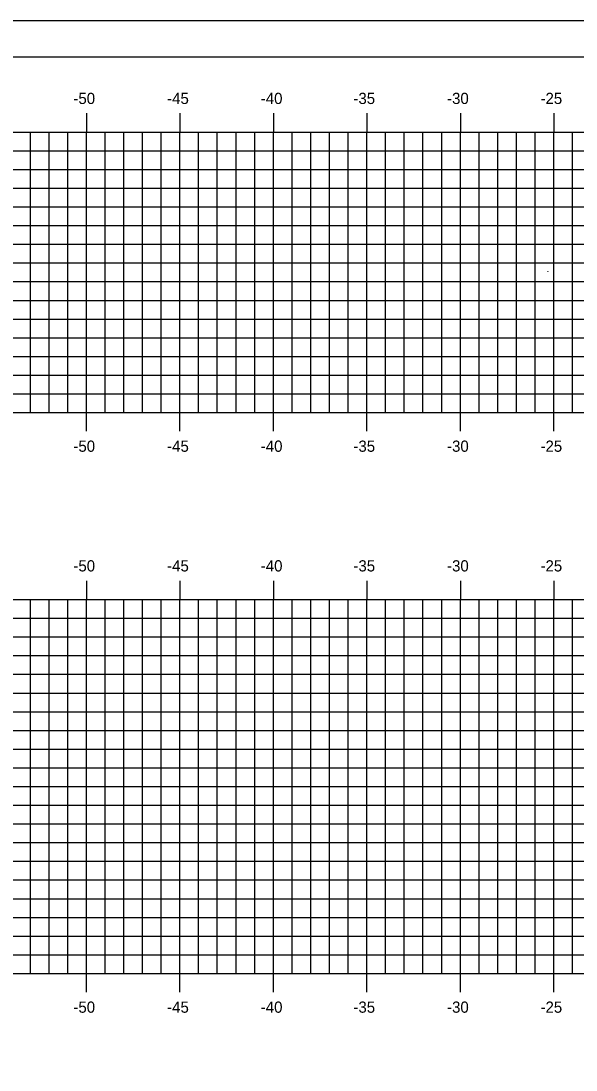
# Model space of a CAD drawing. Extents: x 1026799 to 1026969, y 394697 to 394807.
# Drawn here: x 1026828.8 to 1026858.5, y 394750.4 to 394806.5 of the extents above; entities that cross this region are included whole.
import ezdxf

# ---------------------------------------------------------------- set-up
doc = ezdxf.new("R2010")
doc.units = 0
for name, color, linetype in [('BORDER', 7, 'Continuous'), ('H_V ANNOTATION', 7, 'Continuous'), ('MAJOR', 7, 'Continuous'), ('MINOR', 7, 'Continuous'), ('PLOT BOUNDARY', 7, 'Continuous'), ('S_Utilities_Hydrant', 7, 'Continuous')]:
    doc.layers.add(name, color=color, linetype=linetype)

msp = doc.modelspace()

# ---------------------------------------------------------------- linework, layer by layer
at = {"layer": 'BORDER'}
msp.add_line((1026967.348, 394804.607), (1026807.348, 394804.607), dxfattribs=at)
at = {"layer": 'MAJOR'}
for p, q in [((1026832.348, 394801.609), (1026832.348, 394800.607)), ((1026837.348, 394801.609), (1026837.348, 394800.607)), ((1026842.348, 394801.609), (1026842.348, 394800.607)), ((1026847.348, 394801.609), (1026847.348, 394800.607)), ((1026852.348, 394801.609), (1026852.348, 394800.607)), ((1026857.348, 394801.609), (1026857.348, 394800.607)), ((1026812.348, 394800.607), (1026952.348, 394800.607)), ((1026832.348, 394785.607), (1026832.348, 394800.607)), ((1026837.348, 394785.607), (1026837.348, 394800.607)), ((1026842.348, 394785.607), (1026842.348, 394800.607)), ((1026847.348, 394785.607), (1026847.348, 394800.607)), ((1026852.348, 394785.607), (1026852.348, 394800.607)), ((1026857.348, 394785.607), (1026857.348, 394800.607)), ((1026812.348, 394795.607), (1026952.348, 394795.607)), ((1026812.348, 394790.607), (1026952.348, 394790.607)), ((1026812.348, 394785.607), (1026952.348, 394785.607)), ((1026832.348, 394784.605), (1026832.348, 394785.607)), ((1026837.348, 394784.605), (1026837.348, 394785.607)), ((1026842.348, 394784.605), (1026842.348, 394785.607)), ((1026847.348, 394784.605), (1026847.348, 394785.607)), ((1026852.348, 394784.605), (1026852.348, 394785.607)), ((1026857.348, 394784.605), (1026857.348, 394785.607)), ((1026832.348, 394776.609), (1026832.348, 394775.607)), ((1026837.348, 394776.609), (1026837.348, 394775.607)), ((1026842.348, 394776.609), (1026842.348, 394775.607)), ((1026847.348, 394776.609), (1026847.348, 394775.607)), ((1026852.348, 394776.609), (1026852.348, 394775.607)), ((1026857.348, 394776.609), (1026857.348, 394775.607)), ((1026812.348, 394775.607), (1026952.348, 394775.607)), ((1026832.348, 394755.607), (1026832.348, 394775.607)), ((1026837.348, 394755.607), (1026837.348, 394775.607)), ((1026842.348, 394755.607), (1026842.348, 394775.607)), ((1026847.348, 394755.607), (1026847.348, 394775.607)), ((1026852.348, 394755.607), (1026852.348, 394775.607)), ((1026857.348, 394755.607), (1026857.348, 394775.607)), ((1026812.348, 394770.607), (1026952.348, 394770.607)), ((1026812.348, 394765.607), (1026952.348, 394765.607)), ((1026812.348, 394760.607), (1026952.348, 394760.607)), ((1026812.348, 394755.607), (1026952.348, 394755.607)), ((1026832.348, 394754.605), (1026832.348, 394755.607)), ((1026837.348, 394754.605), (1026837.348, 394755.607)), ((1026842.348, 394754.605), (1026842.348, 394755.607)), ((1026847.348, 394754.605), (1026847.348, 394755.607)), ((1026852.348, 394754.605), (1026852.348, 394755.607)), ((1026857.348, 394754.605), (1026857.348, 394755.607))]:
    msp.add_line(p, q, dxfattribs=at)
at = {"layer": 'MINOR'}
for p, q in [((1026829.348, 394785.607), (1026829.348, 394800.607)), ((1026830.348, 394785.607), (1026830.348, 394800.607)), ((1026831.348, 394785.607), (1026831.348, 394800.607)), ((1026833.348, 394785.607), (1026833.348, 394800.607)), ((1026834.348, 394785.607), (1026834.348, 394800.607)), ((1026835.348, 394785.607), (1026835.348, 394800.607)), ((1026836.348, 394785.607), (1026836.348, 394800.607)), ((1026838.348, 394785.607), (1026838.348, 394800.607)), ((1026839.348, 394785.607), (1026839.348, 394800.607)), ((1026840.348, 394785.607), (1026840.348, 394800.607)), ((1026841.348, 394785.607), (1026841.348, 394800.607)), ((1026843.348, 394785.607), (1026843.348, 394800.607)), ((1026844.348, 394785.607), (1026844.348, 394800.607)), ((1026845.348, 394785.607), (1026845.348, 394800.607)), ((1026846.348, 394785.607), (1026846.348, 394800.607)), ((1026848.348, 394785.607), (1026848.348, 394800.607)), ((1026849.348, 394785.607), (1026849.348, 394800.607)), ((1026850.348, 394785.607), (1026850.348, 394800.607)), ((1026851.348, 394785.607), (1026851.348, 394800.607)), ((1026853.348, 394785.607), (1026853.348, 394800.607)), ((1026854.348, 394785.607), (1026854.348, 394800.607)), ((1026855.348, 394785.607), (1026855.348, 394800.607)), ((1026856.348, 394785.607), (1026856.348, 394800.607)), ((1026858.348, 394785.607), (1026858.348, 394800.607)), ((1026812.348, 394799.607), (1026952.348, 394799.607)), ((1026812.348, 394798.607), (1026952.348, 394798.607)), ((1026812.348, 394797.607), (1026952.348, 394797.607)), ((1026812.348, 394796.607), (1026952.348, 394796.607)), ((1026812.348, 394794.607), (1026952.348, 394794.607)), ((1026812.348, 394793.607), (1026952.348, 394793.607)), ((1026812.348, 394792.607), (1026952.348, 394792.607)), ((1026812.348, 394791.607), (1026952.348, 394791.607)), ((1026812.348, 394789.607), (1026952.348, 394789.607)), ((1026812.348, 394788.607), (1026952.348, 394788.607)), ((1026812.348, 394787.607), (1026952.348, 394787.607)), ((1026812.348, 394786.607), (1026952.348, 394786.607)), ((1026829.348, 394755.607), (1026829.348, 394775.607)), ((1026830.348, 394755.607), (1026830.348, 394775.607)), ((1026831.348, 394755.607), (1026831.348, 394775.607)), ((1026833.348, 394755.607), (1026833.348, 394775.607)), ((1026834.348, 394755.607), (1026834.348, 394775.607)), ((1026835.348, 394755.607), (1026835.348, 394775.607)), ((1026836.348, 394755.607), (1026836.348, 394775.607)), ((1026838.348, 394755.607), (1026838.348, 394775.607)), ((1026839.348, 394755.607), (1026839.348, 394775.607)), ((1026840.348, 394755.607), (1026840.348, 394775.607)), ((1026841.348, 394755.607), (1026841.348, 394775.607)), ((1026843.348, 394755.607), (1026843.348, 394775.607)), ((1026844.348, 394755.607), (1026844.348, 394775.607)), ((1026845.348, 394755.607), (1026845.348, 394775.607)), ((1026846.348, 394755.607), (1026846.348, 394775.607)), ((1026848.348, 394755.607), (1026848.348, 394775.607)), ((1026849.348, 394755.607), (1026849.348, 394775.607)), ((1026850.348, 394755.607), (1026850.348, 394775.607)), ((1026851.348, 394755.607), (1026851.348, 394775.607)), ((1026853.348, 394755.607), (1026853.348, 394775.607)), ((1026854.348, 394755.607), (1026854.348, 394775.607)), ((1026855.348, 394755.607), (1026855.348, 394775.607)), ((1026856.348, 394755.607), (1026856.348, 394775.607)), ((1026858.348, 394755.607), (1026858.348, 394775.607)), ((1026812.348, 394774.607), (1026952.348, 394774.607)), ((1026812.348, 394773.607), (1026952.348, 394773.607)), ((1026812.348, 394772.607), (1026952.348, 394772.607)), ((1026812.348, 394771.607), (1026952.348, 394771.607)), ((1026812.348, 394769.607), (1026952.348, 394769.607)), ((1026812.348, 394768.607), (1026952.348, 394768.607)), ((1026812.348, 394767.607), (1026952.348, 394767.607)), ((1026812.348, 394766.607), (1026952.348, 394766.607)), ((1026812.348, 394764.607), (1026952.348, 394764.607)), ((1026812.348, 394763.607), (1026952.348, 394763.607)), ((1026812.348, 394762.607), (1026952.348, 394762.607)), ((1026812.348, 394761.607), (1026952.348, 394761.607)), ((1026812.348, 394759.607), (1026952.348, 394759.607)), ((1026812.348, 394758.607), (1026952.348, 394758.607)), ((1026812.348, 394757.607), (1026952.348, 394757.607)), ((1026812.348, 394756.607), (1026952.348, 394756.607))]:
    msp.add_line(p, q, dxfattribs=at)
at = {"layer": 'PLOT BOUNDARY'}
msp.add_lwpolyline([(1026799.254, 394696.548), (1026969.254, 394696.548), (1026969.254, 394806.548), (1026799.254, 394806.548)], close=True, dxfattribs=at)
at = {"layer": 'S_Utilities_Hydrant'}
for p, q in [((1026857.017, 394793.161), (1026857.02, 394793.161)), ((1026857.017, 394793.161), (1026857.017, 394793.161)), ((1026857.017, 394793.161), (1026857.017, 394793.161)), ((1026857.017, 394793.161), (1026857.017, 394793.161)), ((1026857.017, 394793.16), (1026857.02, 394793.16)), ((1026857.017, 394793.16), (1026857.017, 394793.16)), ((1026857.017, 394793.16), (1026857.017, 394793.16)), ((1026857.017, 394793.16), (1026857.017, 394793.154)), ((1026857.017, 394793.154), (1026857.02, 394793.154)), ((1026857.017, 394793.154), (1026857.02, 394793.154)), ((1026857.02, 394793.154), (1026857.017, 394793.154)), ((1026857.017, 394793.154), (1026857.02, 394793.154)), ((1026857.017, 394793.154), (1026857.017, 394793.154)), ((1026857.017, 394793.154), (1026857.017, 394793.154)), ((1026857.017, 394793.154), (1026857.017, 394793.154)), ((1026857.017, 394793.154), (1026857.017, 394793.154)), ((1026857.017, 394793.154), (1026857.017, 394793.153)), ((1026857.018, 394793.162), (1026857.018, 394793.162)), ((1026857.018, 394793.162), (1026857.019, 394793.162)), ((1026857.019, 394793.162), (1026857.018, 394793.162)), ((1026857.018, 394793.161), (1026857.018, 394793.161)), ((1026857.018, 394793.161), (1026857.019, 394793.161)), ((1026857.018, 394793.154), (1026857.018, 394793.154)), ((1026857.018, 394793.154), (1026857.018, 394793.154)), ((1026857.018, 394793.154), (1026857.018, 394793.154)), ((1026857.018, 394793.154), (1026857.018, 394793.154)), ((1026857.019, 394793.162), (1026857.019, 394793.162)), ((1026857.019, 394793.161), (1026857.02, 394793.161)), ((1026857.019, 394793.161), (1026857.019, 394793.161)), ((1026857.019, 394793.161), (1026857.019, 394793.161)), ((1026857.019, 394793.16), (1026857.019, 394793.16)), ((1026857.019, 394793.16), (1026857.019, 394793.16)), ((1026857.019, 394793.154), (1026857.019, 394793.154)), ((1026857.019, 394793.154), (1026857.019, 394793.154)), ((1026857.019, 394793.154), (1026857.019, 394793.154)), ((1026857.019, 394793.154), (1026857.019, 394793.154)), ((1026857.02, 394793.161), (1026857.02, 394793.16)), ((1026857.02, 394793.158), (1026857.02, 394793.16)), ((1026857.02, 394793.158), (1026857.02, 394793.16)), ((1026857.02, 394793.16), (1026857.02, 394793.16)), ((1026857.02, 394793.16), (1026857.02, 394793.16)), ((1026857.02, 394793.16), (1026857.02, 394793.158)), ((1026857.02, 394793.16), (1026857.02, 394793.16)), ((1026857.02, 394793.16), (1026857.02, 394793.154)), ((1026857.02, 394793.159), (1026857.02, 394793.159)), ((1026857.02, 394793.159), (1026857.02, 394793.159)), ((1026857.02, 394793.159), (1026857.02, 394793.159)), ((1026857.02, 394793.159), (1026857.02, 394793.159)), ((1026857.02, 394793.159), (1026857.02, 394793.159)), ((1026857.02, 394793.159), (1026857.02, 394793.159)), ((1026857.02, 394793.159), (1026857.02, 394793.159)), ((1026857.02, 394793.158), (1026857.02, 394793.158)), ((1026857.02, 394793.158), (1026857.02, 394793.158)), ((1026857.02, 394793.158), (1026857.02, 394793.158)), ((1026857.02, 394793.154), (1026857.02, 394793.154)), ((1026857.02, 394793.154), (1026857.02, 394793.154)), ((1026857.02, 394793.154), (1026857.02, 394793.154)), ((1026857.02, 394793.154), (1026857.02, 394793.154)), ((1026857.02, 394793.154), (1026857.02, 394793.153))]:
    msp.add_line(p, q, dxfattribs=at)
for points in [[(1026857.017, 394793.16), (1026857.017, 394793.161), (1026857.017, 394793.161)], [(1026857.017, 394793.161), (1026857.017, 394793.161), (1026857.017, 394793.161), (1026857.017, 394793.161), (1026857.017, 394793.161), (1026857.017, 394793.161), (1026857.017, 394793.161)], [(1026857.02, 394793.16), (1026857.02, 394793.16), (1026857.017, 394793.16), (1026857.017, 394793.16)], [(1026857.017, 394793.16), (1026857.017, 394793.16), (1026857.017, 394793.16), (1026857.017, 394793.16)], [(1026857.017, 394793.16), (1026857.017, 394793.16), (1026857.017, 394793.16), (1026857.017, 394793.16), (1026857.017, 394793.16), (1026857.017, 394793.16), (1026857.017, 394793.16)], [(1026857.017, 394793.154), (1026857.017, 394793.154), (1026857.017, 394793.154), (1026857.017, 394793.154), (1026857.017, 394793.154), (1026857.017, 394793.154), (1026857.017, 394793.154)], [(1026857.017, 394793.154), (1026857.017, 394793.154), (1026857.017, 394793.154), (1026857.017, 394793.154)], [(1026857.017, 394793.154), (1026857.017, 394793.154), (1026857.017, 394793.154), (1026857.017, 394793.154), (1026857.017, 394793.154), (1026857.017, 394793.154), (1026857.017, 394793.154)], [(1026857.018, 394793.162), (1026857.018, 394793.162), (1026857.019, 394793.162), (1026857.019, 394793.162)], [(1026857.018, 394793.161), (1026857.018, 394793.161), (1026857.018, 394793.161), (1026857.018, 394793.161)], [(1026857.018, 394793.159), (1026857.018, 394793.159), (1026857.019, 394793.159), (1026857.018, 394793.159), (1026857.018, 394793.159), (1026857.018, 394793.159)], [(1026857.018, 394793.154), (1026857.018, 394793.154), (1026857.018, 394793.154), (1026857.018, 394793.154), (1026857.018, 394793.154), (1026857.018, 394793.154), (1026857.018, 394793.154)], [(1026857.018, 394793.154), (1026857.018, 394793.154), (1026857.018, 394793.154), (1026857.018, 394793.154)], [(1026857.018, 394793.154), (1026857.018, 394793.154), (1026857.018, 394793.154), (1026857.018, 394793.154), (1026857.018, 394793.154), (1026857.018, 394793.154), (1026857.018, 394793.154)], [(1026857.019, 394793.161), (1026857.019, 394793.161), (1026857.019, 394793.161), (1026857.019, 394793.161)], [(1026857.019, 394793.161), (1026857.019, 394793.161), (1026857.019, 394793.161), (1026857.019, 394793.161), (1026857.019, 394793.161), (1026857.019, 394793.161), (1026857.019, 394793.161)], [(1026857.019, 394793.16), (1026857.019, 394793.16), (1026857.019, 394793.16), (1026857.019, 394793.16)], [(1026857.019, 394793.16), (1026857.019, 394793.16), (1026857.019, 394793.16), (1026857.019, 394793.16), (1026857.019, 394793.16), (1026857.019, 394793.16), (1026857.019, 394793.16)], [(1026857.019, 394793.154), (1026857.019, 394793.154), (1026857.019, 394793.154), (1026857.019, 394793.154), (1026857.019, 394793.154), (1026857.019, 394793.154), (1026857.019, 394793.154)], [(1026857.019, 394793.154), (1026857.019, 394793.154), (1026857.019, 394793.154), (1026857.019, 394793.154)], [(1026857.019, 394793.154), (1026857.019, 394793.154), (1026857.019, 394793.154), (1026857.019, 394793.154), (1026857.019, 394793.154), (1026857.019, 394793.154), (1026857.019, 394793.154)], [(1026857.02, 394793.159), (1026857.02, 394793.159), (1026857.02, 394793.159), (1026857.02, 394793.159)], [(1026857.02, 394793.154), (1026857.02, 394793.154), (1026857.02, 394793.154), (1026857.02, 394793.154), (1026857.02, 394793.154), (1026857.02, 394793.154), (1026857.02, 394793.154)], [(1026857.02, 394793.154), (1026857.02, 394793.154), (1026857.02, 394793.154), (1026857.02, 394793.154)], [(1026857.02, 394793.154), (1026857.02, 394793.154), (1026857.02, 394793.154), (1026857.02, 394793.154), (1026857.02, 394793.154), (1026857.02, 394793.154), (1026857.02, 394793.154)]]:
    msp.add_lwpolyline(points, dxfattribs=at)
for radius in [0.000526, 0.000426]:
    msp.add_circle((1026857.018, 394793.159), radius, dxfattribs=at)
for centre, radius, start, end in [((1026857.017, 394793.161), 0.0000637, 96.9921, 168.8028), ((1026857.018, 394793.161), 0.000314, 104.4243, 167.4801), ((1026857.017, 394793.161), 0.0000275, 32.9144, 129.4939), ((1026857.017, 394793.161), 0.0000938, 60.0007, 120.0007), ((1026857.017, 394793.161), 0.0000275, 50.5064, 147.0859), ((1026857.017, 394793.16), 0.0000637, 186.9921, 258.8028), ((1026857.017, 394793.16), 0.0000275, 212.9144, 309.4939), ((1026857.017, 394793.16), 0.0000938, 240.0007, 300.0007), ((1026857.017, 394793.16), 0.0000275, 230.5064, 327.0859), ((1026857.017, 394793.154), 0.000469, 143.1301, 216.8699), ((1026857.017, 394793.154), 0.0000275, 32.9144, 129.4939), ((1026857.017, 394793.154), 0.0000938, 60.0007, 120.0007), ((1026857.017, 394793.154), 0.0000275, 50.5064, 147.0859), ((1026857.017, 394793.154), 0.0000275, 212.9144, 309.4939), ((1026857.017, 394793.154), 0.0000938, 240.0007, 300.0007), ((1026857.017, 394793.154), 0.0000275, 230.5064, 327.0859), ((1026857.018, 394793.162), 0.0000637, 96.9921, 168.8028), ((1026857.018, 394793.161), 0.0000634, 96.6574, 168.4681), ((1026857.018, 394793.154), 0.0000275, 32.9144, 129.4939), ((1026857.018, 394793.154), 0.0000938, 60.0007, 120.0007), ((1026857.018, 394793.154), 0.0000275, 50.5064, 147.0859), ((1026857.018, 394793.154), 0.0000275, 212.9144, 309.4939), ((1026857.018, 394793.154), 0.0000938, 240.0007, 300.0007), ((1026857.018, 394793.154), 0.0000275, 230.5064, 327.0859), ((1026857.019, 394793.162), 0.0000633, 11.5884, 83.3991), ((1026857.019, 394793.161), 0.0000637, 11.1972, 83.0079), ((1026857.019, 394793.161), 0.000314, 12.5199, 75.5757), ((1026857.019, 394793.161), 0.0000275, 50.5061, 147.0856), ((1026857.019, 394793.161), 0.0000938, 59.9993, 119.9993), ((1026857.019, 394793.161), 0.0000275, 32.9141, 129.4936), ((1026857.019, 394793.16), 0.0000275, 230.5061, 327.0856), ((1026857.019, 394793.16), 0.0000938, 239.9993, 299.9993), ((1026857.019, 394793.16), 0.0000275, 212.9141, 309.4936), ((1026857.019, 394793.154), 0.0000275, 32.9144, 129.4939), ((1026857.019, 394793.154), 0.0000938, 60.0007, 120.0007), ((1026857.019, 394793.154), 0.0000275, 50.5064, 147.0859), ((1026857.019, 394793.154), 0.0000275, 212.9144, 309.4939), ((1026857.019, 394793.154), 0.0000938, 240.0007, 300.0007), ((1026857.019, 394793.154), 0.0000275, 230.5064, 327.0859), ((1026857.02, 394793.161), 0.0000637, 11.1972, 83.0079), ((1026857.02, 394793.16), 0.0000637, 281.1972, 353.0079), ((1026857.02, 394793.159), 0.0000637, 11.1972, 83.0079), ((1026857.02, 394793.16), 0.000349, 200.4701, 262.5766), ((1026857.02, 394793.159), 0.00039, 74.2628, 77.9381), ((1026857.02, 394793.159), 0.0000119, 53.1301, 74.2628), ((1026857.02, 394793.159), 0.0000313, 45, 53.1301), ((1026857.02, 394793.159), 0.0000313, 36.8699, 45), ((1026857.02, 394793.159), 0.0000084, 216.8699, 245.556), ((1026857.02, 394793.159), 0.0000227, 245.556, 262.875), ((1026857.02, 394793.159), 0.0000575, 262.875, 270), ((1026857.02, 394793.159), 0.0000229, 270, 281.3099), ((1026857.02, 394793.159), 0.0000365, 281.3099, 288.435), ((1026857.02, 394793.159), 0.000028, 288.435, 296.5651), ((1026857.02, 394793.159), 0.000048, 111.8014, 116.565), ((1026857.02, 394793.159), 0.0000961, 108.4349, 111.8014), ((1026857.02, 394793.159), 0.0000112, 82.875, 108.435), ((1026857.02, 394793.159), 0.00000316, 33.6901, 82.875), ((1026857.02, 394793.159), 0.000058, 213.6901, 216.8699), ((1026857.02, 394793.159), 0.000183, 216.8699, 218.6598), ((1026857.02, 394793.159), 0.0000347, 29.3578, 38.6598), ((1026857.02, 394793.159), 0.00000764, 9.4623, 29.3578), ((1026857.02, 394793.159), 0.00026, 8.5659, 9.4623), ((1026857.02, 394793.159), 0.0000288, 5.8719, 8.5659), ((1026857.02, 394793.159), 0.0000433, 2.2818, 5.8719), ((1026857.02, 394793.159), 0.000428, 1.1407, 2.2818), ((1026857.02, 394793.159), 0.000285, 0.285, 1.1407), ((1026857.018, 394793.159), 0.00257, 0, 0.285), ((1026857.02, 394793.159), 0.00039, 282.0619, 285.7372), ((1026857.02, 394793.159), 0.0000119, 285.7372, 306.8699), ((1026857.02, 394793.159), 0.0000313, 306.8699, 315), ((1026857.02, 394793.159), 0.0000313, 315, 323.1301), ((1026857.02, 394793.159), 0.0000084, 114.444, 143.1301), ((1026857.02, 394793.159), 0.0000227, 97.125, 114.444), ((1026857.02, 394793.159), 0.0000575, 90, 97.125), ((1026857.02, 394793.159), 0.0000229, 78.6901, 90), ((1026857.02, 394793.159), 0.0000365, 71.5651, 78.6901), ((1026857.02, 394793.159), 0.000028, 63.4349, 71.5651), ((1026857.02, 394793.159), 0.000048, 243.435, 248.1986), ((1026857.02, 394793.159), 0.0000961, 248.1986, 251.5651), ((1026857.02, 394793.159), 0.0000112, 251.565, 277.125), ((1026857.02, 394793.159), 0.00000316, 277.125, 326.3099), ((1026857.02, 394793.159), 0.000058, 143.1301, 146.3099), ((1026857.02, 394793.159), 0.000183, 141.3402, 143.1301), ((1026857.02, 394793.159), 0.0000347, 321.3402, 330.6422), ((1026857.02, 394793.159), 0.00000764, 330.6422, 350.5377), ((1026857.02, 394793.159), 0.00026, 350.5377, 351.4341), ((1026857.02, 394793.159), 0.0000288, 351.4341, 354.1282), ((1026857.02, 394793.159), 0.0000433, 354.1282, 357.7182), ((1026857.02, 394793.159), 0.000428, 357.7182, 358.8593), ((1026857.02, 394793.159), 0.000285, 358.8593, 359.715), ((1026857.018, 394793.159), 0.00257, 359.715, 0), ((1026857.02, 394793.158), 0.000064, 281.4565, 353.2672), ((1026857.02, 394793.158), 0.000349, 97.4234, 159.5299), ((1026857.019, 394793.154), 0.000469, 323.1301, 36.8699), ((1026857.02, 394793.154), 0.0000275, 32.9144, 129.4939), ((1026857.02, 394793.154), 0.0000938, 60.0007, 120.0007), ((1026857.02, 394793.154), 0.0000275, 50.5064, 147.0859), ((1026857.02, 394793.154), 0.0000275, 212.9144, 309.4939), ((1026857.02, 394793.154), 0.0000938, 240.0007, 300.0007), ((1026857.02, 394793.154), 0.0000275, 230.5064, 327.0859)]:
    msp.add_arc(centre, radius, start, end, dxfattribs=at)

# ---------------------------------------------------------------- texts
at = {"layer": 'H_V ANNOTATION'}
for s, p in [('-50', (1026831.652, 394802.107)), ('-45', (1026836.665, 394802.107)), ('-40', (1026841.673, 394802.107)), ('-35', (1026846.628, 394802.107)), ('-30', (1026851.636, 394802.107)), ('-25', (1026856.633, 394802.107)), ('-50', (1026831.652, 394783.507)), ('-45', (1026836.665, 394783.507)), ('-40', (1026841.673, 394783.507)), ('-35', (1026846.628, 394783.507)), ('-30', (1026851.636, 394783.507)), ('-25', (1026856.633, 394783.507)), ('-50', (1026831.652, 394777.107)), ('-45', (1026836.665, 394777.107)), ('-40', (1026841.673, 394777.107)), ('-35', (1026846.628, 394777.107)), ('-30', (1026851.636, 394777.107)), ('-25', (1026856.633, 394777.107)), ('-50', (1026831.652, 394753.507)), ('-45', (1026836.665, 394753.507)), ('-40', (1026841.673, 394753.507)), ('-35', (1026846.628, 394753.507)), ('-30', (1026851.636, 394753.507)), ('-25', (1026856.633, 394753.507))]:
    msp.add_text(s, height=0.6, dxfattribs=at).set_placement(p)

doc.saveas('drawing.dxf')
